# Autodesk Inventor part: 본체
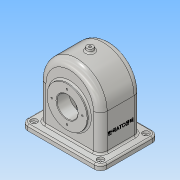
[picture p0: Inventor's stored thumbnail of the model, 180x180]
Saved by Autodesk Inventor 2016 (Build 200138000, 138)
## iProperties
Created: 2018-08
Part Number: 본체
Material: 알루미늄 6061
Document SubType Name: Modeling
Designer: Administrator
Density: 2.7 g/cm^3
Appearance: 알루미늄 - 평지
Mass: 1091.9 g
Surface Area: 1182.65 cm^2
Volume: 404.407 cm^3
Author: Administrator
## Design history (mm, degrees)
sketch "스케치1"
  geometry: L1 (-75, 55)-(75, 55); L2 (75, 55)-(75, -55); L3 (75, -55)-(-75, -55); L4 (-75, -55)-(-75, 55); L5 (-75, 55)-(75, -55); L6 (75, 55)-(-75, -55); 1 further point
  constraints: 12 end point, 2 midpoint, 2 parallel, 1 horizontal, 1 perpendicular
  dimensions: "d0" = 150 distance of L2.end L3.end; "d1" = 110 distance of L1.end L2.end
extrude "돌출1" new body sketch "스케치1" distance "d2" = 10; taper "d3" = 0 deg
sketch "스케치2"
  geometry: L1 (-75, 0)-(75, 0) reference; L2 (58, 78)-(58, 10); L3 (-75, 10)-(75, 10) reference; L4 (-58, 78)-(-58, 10); A1 r 58 centre (0, 78) between (58, 78) and (-58, 78); 2 further points
  constraints: 4 end point, 2 point on circle, 2 point on line, 1 centre point, 1 midpoint, 1 parallel, 1 tangent, 1 vertical, 1 vertical alignment
  dimensions: "d4" = 58 radius of A1; "d5" = 78 distance from line of L1 A1.centre; "d6" = 68 distance of L2.start L2.end
extrude "돌출2" join sketch "스케치2" stored distance "d7" = 77; taper "d8" = 0 deg
feature "쉘2" dims "d12" = 6, "d13" = 15, "d14" = 5
fillet "모깎기1" dims "d15" = 12
sketch "스케치3"
  geometry: L1 (63, 0)-(-63, 0) reference; C1 r 38 at (0, 65); 2 further points
  constraints: 1 centre point, 1 midpoint, 1 vertical alignment
  dimensions: "d17" = 76 diameter of C1; "d18" = 65 distance from line of L1 C1.centre
extrude "돌출3" join sketch "스케치3" distance "d19" = 5; taper "d20" = 0 deg
sketch "스케치4"
  geometry: L1 (-63, 0)-(63, 0) reference; C1 r 38 at (0, -65); 2 further points
  constraints: 1 centre point, 1 midpoint, 1 vertical alignment
  dimensions: "d21" = 76 diameter of C1; "d22" = 65 distance from line of L1 C1.centre
extrude "돌출4" join sketch "스케치4" distance "d23" = 10; taper "d24" = 0 deg
hole "구멍1" diameter "d36" = 40; stored, may be unused: countersink angle "d40" = 90 deg, drill point angle "d42" = 118 deg; dims "d34" = 10, "d35" = 10, "d37" = 6, "d38" = 4, "d39" = 2, "d41" = 8
sketch "스케치6"
  geometry: L1 (63, -65)-(-63, -65) reference; 3 further points
  constraints: 1 midpoint, 1 vertical alignment
  dimensions: "d43" = 94 distance from line of L1 point (0, 29)
hole "구멍2" sketch "스케치6" at (0, 29) diameter "d44" = 3.242; stored, may be unused: countersink angle "d48" = 90 deg, drill point angle "d50" = 118 deg; dims "d45" = 8, "d46" = 4, "d47" = 2, "d49" = 10
sketch "스케치7"
  geometry: L1 (-63, 65)-(63, 65) reference; 3 further points
  constraints: 1 midpoint, 1 vertical alignment
  dimensions: "d54" = 94 distance from line of L1 point (0, -29)
hole "구멍3" sketch "스케치7" at (0, -29) diameter "d55" = 3.242; stored, may be unused: countersink angle "d59" = 90 deg, drill point angle "d61" = 118 deg; dims "d56" = 8, "d57" = 4, "d58" = 2, "d60" = 10
fillet "모깎기2" dims "d65" = 13
sketch "스케치8"
  geometry: A1 r 12 centre (-63, -43) between (-75, -43) and (-63, -55) reference; 2 further points
  constraints: 1 coincident
hole "구멍4" sketch "스케치8" at (-63, -43) diameter "d66" = 5; stored, may be unused: countersink angle "d70" = 90 deg, drill point angle "d72" = 118 deg; dims "d67" = 20, "d68" = 12, "d69" = 4, "d71" = 10
fillet "모깎기3" dims "d73" = 8
node "작업 평면1"
sketch "스케치9"
  geometry: C1 r 6 at (0, 0); 1 further point
  constraints: 1 centre point, 1 coincident
  dimensions: "d75" = 12 diameter of C1
extrude "돌출5" join sketch "스케치9" stored distance "d76" = 10; taper "d77" = 5 deg
hole "구멍5" diameter "d80" = 4.459; stored, may be unused: countersink angle "d84" = 90 deg, drill point angle "d86" = 118 deg; dims "d78" = 10, "d79" = 10, "d81" = 25, "d82" = 12, "d83" = 4, "d85" = 12.8
sketch "스케치10"
  geometry: L1 (78, 68.5)-(78, -17.5) reference; L2 (0, -13)-(68, -13) reference; 2 further points
  constraints: 1 other
  dimensions: "d87" = 40 distance from line of L1 point (38, 25.5); "d88" = 38.5 distance from line of L2 point (38, 25.5)
feature "엠보싱1" sketch "스케치10" dims "d89" = 0.5, "d90" = 0
chamfer "모따기1" distance "d92" = 1; stored, may be unused: second distance "d93" = 2, angle "d94" = 45 deg
chamfer "모따기2" distance "d95" = 1; stored, may be unused: second distance "d96" = 2, angle "d97" = 45 deg
fillet "모깎기5" dims "d98" = 3
fillet "모깎기6" dims "d99" = 3
fillet "모깎기7" dims "d100" = 3
fillet "모깎기8" dims "d101" = 3
sketch "스케치11"
  geometry: L1 (-70.271, 65)-(73.342, 65); L2 (25.5, 0)-(-25.5, 0) reference; L3 (-43.5, 65)-(-19.5, 65); L4 (-19.5, 65)-(-19.5, 93); L5 (-19.5, 93)-(-33.5, 104.747); L6 (-33.5, 104.747)-(-33.5, 103); L7 (-33.5, 103)-(-43.5, 103); L8 (-43.5, 103)-(-43.5, 65); L9 (-43.5, 103)-(-43.5, 27) reference; 2 further points
  constraints: 14 end point, 3 horizontal, 2 perpendicular, 2 point on line, 1 midpoint, 1 parallel
  dimensions: "d107" = 65 distance between parallel lines of L2 L1; "d108" = 24 distance of L3.start L3.end; "d109" = 38 distance of L7.end L3.start; "d110" = 28 distance of L3.end L4.end; "d111" = 50 deg angle of L4 L5; "d112" = 10 distance of L6.end L7.end
revolve "회전2" sketch "스케치11" stored, may be unused: angle "d113" = 90 deg
sketch "스케치12"
  geometry: L1 (63, -65)-(-63, -65) reference; C1 r 20 at (0, 0); 2 further points
  constraints: 1 centre point, 1 coincident, 1 midpoint, 1 vertical alignment
  dimensions: "d115" = 40 diameter of C1; "d116" = 65 distance from line of L1 C1.centre
extrude "돌출6" cut sketch "스케치12" stored distance "d117" = 10; taper "d118" = 0 deg
chamfer "모따기3" distance "d119" = 1; stored, may be unused: second distance "d120" = 2, angle "d121" = 45 deg
sketch "스케치13"
  geometry: L1 (63, -65)-(-63, -65) reference; 3 further points
  constraints: 1 midpoint, 1 vertical alignment
  dimensions: "d122" = 94 distance from line of L1 point (0, 29)
hole "구멍6" sketch "스케치13" at (0, 29) diameter "d123" = 3.242; stored, may be unused: countersink angle "d127" = 90 deg, drill point angle "d129" = 118 deg; dims "d124" = 8, "d125" = 12, "d126" = 4, "d128" = 10
node "솔리드1"
pattern_circular "원형 패턴2" dims angle "d63" = 360 deg
mirror "대칭1"
mirror "대칭2"
pattern_circular "원형 패턴3" dims angle "d131" = 360 deg
other parameters: "d74" = 142
